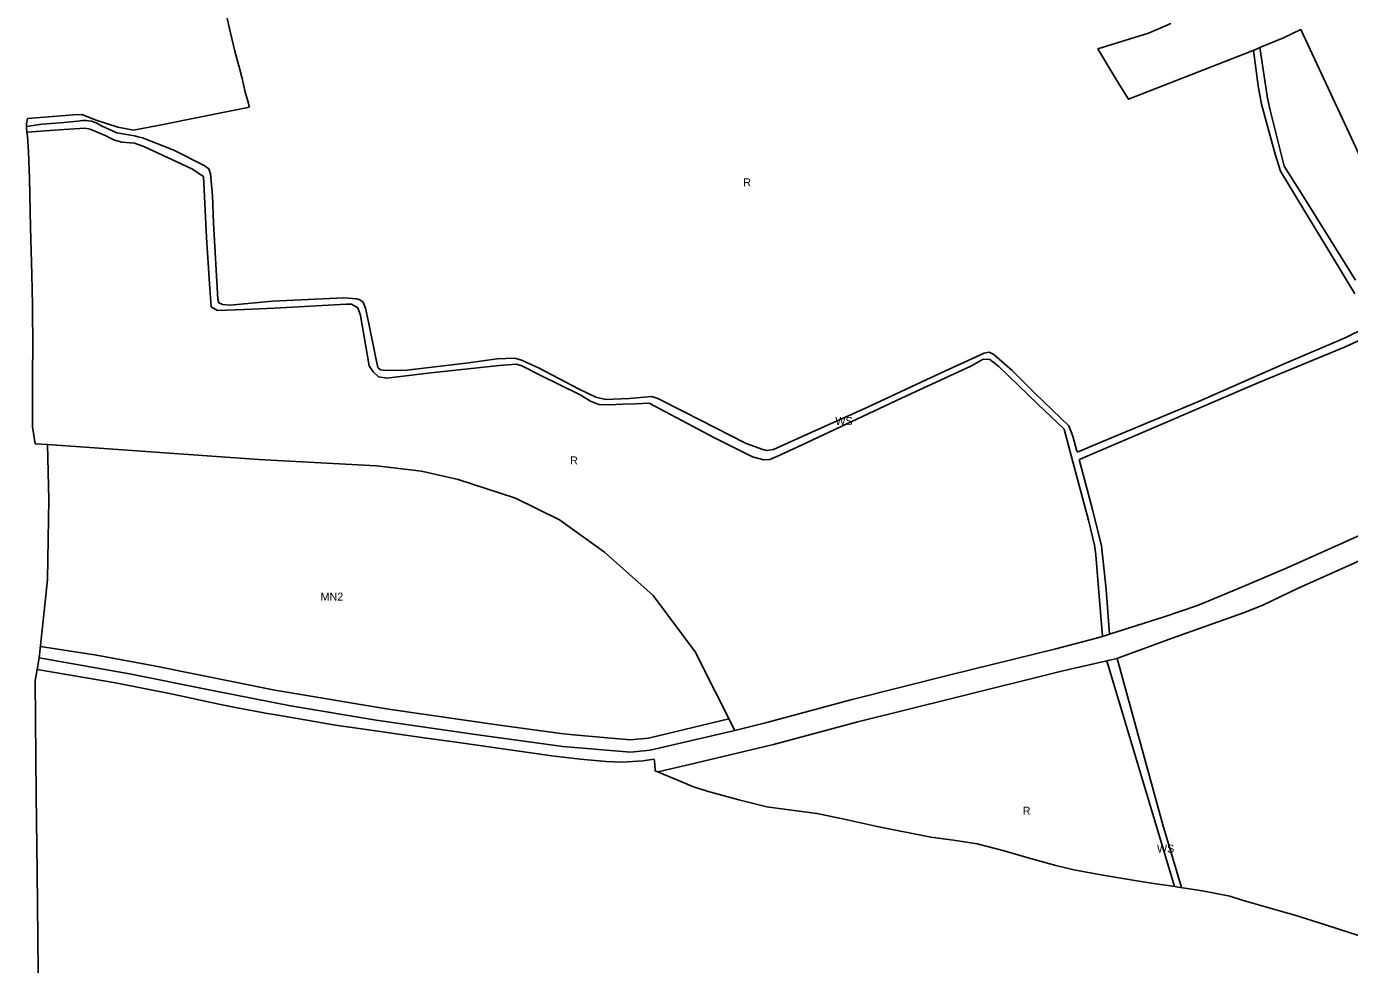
# Model space of a CAD drawing. Extents: x 7435758 to 7439981, y 5550649 to 5554049.
# Drawn here: x 7435758 to 7436617, y 5551099 to 5551708 of the extents above; entities that cross this region are included whole.
import ezdxf

# ---------------------------------------------------------------- set-up
doc = ezdxf.new("R2010")
doc.units = 0
for name, color, linetype in [('#Ruszcza', 7, 'Continuous'), ('_Tereny dla których obowiązuje MPZP', 7, 'Continuous'), ('linie_rozgraniczające', 7, 'Continuous'), ('linie_zabudowy_nieprzekraczalne', 7, 'Continuous'), ('oznaczenia_przeznaczen', 7, 'Continuous')]:
    doc.layers.add(name, color=color, linetype=linetype)

msp = doc.modelspace()

# ---------------------------------------------------------------- linework, layer by layer
at = {"layer": '#Ruszcza'}
for points in [[(7435764.91, 5551290.44), (7435763.61, 5551283.25), (7435764.25, 5551208.63), (7435764.51, 5551191.99), (7435764.91, 5551158.91), (7435765.29, 5551116.27), (7435765.64, 5551071.82), (7435762.19, 5551071.7), (7435762.39, 5551040.78), (7435762.64, 5551012.85), (7435763.34, 5550965.24), (7435763.42, 5550948.08), (7435763.51, 5550925.13)], [(7436649.61, 5551109.17), (7436611.08, 5551121.48), (7436601.18, 5551124.65), (7436581.32, 5551130.87), (7436576.56, 5551132.28), (7436547.71, 5551140.5), (7436539.6, 5551143.01), (7436521.94, 5551146.66), (7436506.12, 5551149.03), (7436503.85, 5551149.37), (7436490.05, 5551151.37), (7436476.69, 5551153.48), (7436457.24, 5551156.77), (7436438.37, 5551160.14), (7436426.54, 5551163.05), (7436407.16, 5551168.39), (7436393.06, 5551172.56), (7436375.57, 5551177.12), (7436360.06, 5551179.5), (7436345.33, 5551181.32), (7436310.46, 5551188.38), (7436291.18, 5551192.72), (7436285.08, 5551194), (7436271.4, 5551196.86), (7436253.31, 5551199.13), (7436240.5, 5551201.01), (7436238.82, 5551201.24), (7436220.63, 5551205.6), (7436200.03, 5551211.4), (7436191.25, 5551214.18), (7436183.03, 5551217.57), (7436180.38, 5551218.68), (7436166.33, 5551224.62), (7436166.04, 5551228.56), (7436165.89, 5551230.71), (7436165.79, 5551232.1), (7436161.13, 5551231.46), (7436158.49, 5551231.09), (7436144.77, 5551230.2), (7436139.82, 5551230.32), (7436134.57, 5551230.57), (7436117.71, 5551232.03), (7436099.24, 5551234.28), (7436038.66, 5551242.88), (7436016.37, 5551246.04), (7435972.54, 5551252.27), (7435958.63, 5551254.24), (7435920.04, 5551260.84), (7435914.57, 5551261.73), (7435894.9, 5551265.52), (7435882.8, 5551267.86), (7435851.87, 5551274.56), (7435815.73, 5551281.6), (7435764.91, 5551290.44)]]:
    msp.add_lwpolyline(points, dxfattribs=at)
at = {"layer": '_Tereny dla których obowiązuje MPZP'}
msp.add_line((7436555, 5551692.66), (7436558.29, 5551694.06), dxfattribs=at)
for points in [[(7436500.87, 5551710.27), (7436500.89, 5551709.81), (7436486.9, 5551703.76), (7436453.97, 5551693.56), (7436466.32, 5551673)], [(7436574.58, 5551700.76), (7436585.89, 5551706.11), (7436720.07, 5551418.24), (7436733.75, 5551423.85)], [(7436558.29, 5551694.06), (7436559.23, 5551694.45), (7436574.58, 5551700.76)], [(7436466.32, 5551673), (7436473.75, 5551660.92), (7436554.78, 5551692.57), (7436555, 5551692.66)]]:
    msp.add_lwpolyline(points, dxfattribs=at)
at = {"layer": 'linie_rozgraniczające'}
for p, q in [((7435890.47, 5551704), (7435887.2, 5551718.12)), ((7435893.21, 5551692.19), (7435890.47, 5551704)), ((7435895.24, 5551685.05), (7435893.21, 5551692.19)), ((7436555, 5551692.66), (7436558.29, 5551694.06)), ((7436555, 5551692.66), (7436558.03, 5551669.7)), ((7436564.11, 5551661.5), (7436559.23, 5551694.45)), ((7435895.94, 5551682.6), (7435895.24, 5551685.05)), ((7435896.63, 5551680.15), (7435895.94, 5551682.6)), ((7435897.99, 5551674.34), (7435896.63, 5551680.15)), ((7435899.35, 5551668.53), (7435897.99, 5551674.34)), ((7436558.03, 5551669.7), (7436560.18, 5551657.72)), ((7435899.85, 5551666.39), (7435899.35, 5551668.53)), ((7435900.35, 5551664.24), (7435899.85, 5551666.39)), ((7435901.24, 5551661.21), (7435900.35, 5551664.24)), ((7435902.14, 5551658.18), (7435901.24, 5551661.21)), ((7436565.91, 5551653.74), (7436564.11, 5551661.5)), ((7435868.1, 5551648.84), (7435902.76, 5551655.75)), ((7435902.45, 5551656.97), (7435902.14, 5551658.18)), ((7435902.76, 5551655.75), (7435902.45, 5551656.97)), ((7436560.18, 5551657.72), (7436569.22, 5551625.29)), ((7436574.95, 5551617.32), (7436565.91, 5551653.74)), ((7435767.94, 5551644.67), (7435757.92, 5551643.27)), ((7435757.94, 5551643.65), (7435758, 5551644.9)), ((7435758, 5551644.9), (7435758.49, 5551648.43)), ((7435758.49, 5551648.43), (7435788.37, 5551650.69)), ((7435771.19, 5551645.01), (7435767.94, 5551644.67)), ((7435779.88, 5551645.64), (7435771.19, 5551645.01)), ((7435791.24, 5551646.61), (7435779.88, 5551645.64)), ((7435788.37, 5551650.69), (7435793.96, 5551650.98)), ((7435794.38, 5551646.99), (7435791.24, 5551646.61)), ((7435793.96, 5551650.98), (7435803.21, 5551647.36)), ((7435796.84, 5551647.11), (7435794.38, 5551646.99)), ((7435798.19, 5551646.94), (7435796.84, 5551647.11)), ((7435800.14, 5551646.67), (7435798.19, 5551646.94)), ((7435803.2, 5551645.66), (7435800.14, 5551646.67)), ((7435807.12, 5551643.49), (7435803.2, 5551645.66)), ((7435803.21, 5551647.36), (7435817.37, 5551642.66)), ((7435827.37, 5551640.72), (7435847.75, 5551644.78)), ((7435847.75, 5551644.78), (7435868.1, 5551648.84)), ((7435757.92, 5551643.27), (7435757.94, 5551643.65)), ((7435757.99, 5551642.39), (7435757.92, 5551643.27)), ((7435758.21, 5551639.4), (7435757.99, 5551642.39)), ((7435758.21, 5551639.4), (7435779.15, 5551640.93)), ((7435758.23, 5551639.18), (7435758.21, 5551639.4)), ((7435758.61, 5551636.84), (7435758.23, 5551639.18)), ((7435759.17, 5551626.65), (7435758.61, 5551636.84)), ((7435779.15, 5551640.93), (7435795.82, 5551642.05)), ((7435795.82, 5551642.05), (7435799.23, 5551641.56)), ((7435799.23, 5551641.56), (7435809.09, 5551637.31)), ((7435814.16, 5551640.14), (7435807.12, 5551643.49)), ((7435809.09, 5551637.31), (7435815.11, 5551634.41)), ((7435816.72, 5551639.15), (7435814.16, 5551640.14)), ((7435828.03, 5551637.18), (7435816.72, 5551639.15)), ((7435817.37, 5551642.66), (7435827.37, 5551640.72)), ((7435830.38, 5551636.51), (7435828.03, 5551637.18)), ((7435833.41, 5551635.84), (7435830.38, 5551636.51)), ((7435853.6, 5551627.74), (7435833.41, 5551635.84)), ((7435815.11, 5551634.41), (7435819.95, 5551632.97)), ((7435819.95, 5551632.97), (7435828.02, 5551632.29)), ((7435828.02, 5551632.29), (7435834.26, 5551630.16)), ((7435834.26, 5551630.16), (7435865.27, 5551615.76)), ((7435873.35, 5551617.92), (7435853.6, 5551627.74)), ((7435759.83, 5551609.39), (7435759.17, 5551626.65)), ((7436569.22, 5551625.29), (7436572.53, 5551614.07)), ((7435865.27, 5551615.76), (7435872.89, 5551610.67)), ((7435872.89, 5551610.67), (7435874.87, 5551571.09)), ((7435876.46, 5551615.78), (7435873.35, 5551617.92)), ((7435877.47, 5551612.43), (7435876.46, 5551615.78)), ((7435878.68, 5551598.14), (7435877.47, 5551612.43)), ((7436572.53, 5551614.07), (7436588.07, 5551588.32)), ((7436588.35, 5551596.16), (7436574.95, 5551617.32)), ((7435760.47, 5551577.65), (7435759.83, 5551609.39)), ((7435879.53, 5551580.33), (7435878.68, 5551598.14)), ((7436621.2, 5551543.41), (7436588.35, 5551596.16)), ((7436588.07, 5551588.32), (7436610.73, 5551551.38)), ((7435761.45, 5551547.11), (7435760.47, 5551577.65)), ((7435882.15, 5551531.1), (7435879.53, 5551580.33)), ((7435874.87, 5551571.09), (7435876.72, 5551541.12)), ((7436610.73, 5551551.38), (7436620.92, 5551534.56)), ((7435761.87, 5551527.04), (7435761.45, 5551547.11)), ((7435876.72, 5551541.12), (7435877.96, 5551526.09)), ((7435761.96, 5551498.45), (7435761.87, 5551527.04)), ((7435877.96, 5551526.09), (7435881.95, 5551523.61)), ((7435881.95, 5551523.61), (7435899.28, 5551524.25)), ((7435882.88, 5551528.61), (7435882.15, 5551531.1)), ((7435885.31, 5551527.58), (7435882.88, 5551528.61)), ((7435890.23, 5551527.15), (7435885.31, 5551527.58)), ((7435917.66, 5551529.65), (7435890.23, 5551527.15)), ((7435899.28, 5551524.25), (7435919.1, 5551525.18)), ((7435964.08, 5551531.85), (7435917.66, 5551529.65)), ((7435919.1, 5551525.18), (7435965.63, 5551527.64)), ((7435972.53, 5551531.18), (7435964.08, 5551531.85)), ((7435965.63, 5551527.64), (7435969.03, 5551527.65)), ((7435969.03, 5551527.65), (7435973.27, 5551525.31)), ((7435974.44, 5551530.63), (7435972.53, 5551531.18)), ((7435973.27, 5551525.31), (7435974.98, 5551520.47)), ((7435976.64, 5551529.09), (7435974.44, 5551530.63)), ((7435978.18, 5551525.13), (7435976.64, 5551529.09)), ((7435980.34, 5551515.16), (7435978.18, 5551525.13)), ((7435974.98, 5551520.47), (7435980.58, 5551487.64)), ((7435984.6, 5551493.84), (7435980.34, 5551515.16)), ((7436614.1, 5551499.83), (7436632.56, 5551508.26)), ((7436628.7, 5551512.83), (7436614.59, 5551505.95)), ((7435761.89, 5551484.88), (7435761.96, 5551498.45)), ((7436558.6, 5551476.88), (7436614.1, 5551499.83)), ((7436614.59, 5551505.95), (7436574.99, 5551489.01)), ((7435986.28, 5551486.61), (7435984.6, 5551493.84)), ((7436044.99, 5551489.56), (7436005.08, 5551484.8)), ((7436063.61, 5551492.14), (7436044.99, 5551489.56)), ((7436075.16, 5551492.61), (7436063.61, 5551492.14)), ((7436079.48, 5551491.4), (7436075.16, 5551492.61)), ((7436090.49, 5551486.44), (7436079.48, 5551491.4)), ((7436379.97, 5551495.99), (7436352.08, 5551483.23)), ((7436371.76, 5551487.67), (7436379.51, 5551492.01)), ((7436379.51, 5551492.01), (7436383.79, 5551491.81)), ((7436383.22, 5551496.5), (7436379.97, 5551495.99)), ((7436386.42, 5551494.99), (7436383.22, 5551496.5)), ((7436383.79, 5551491.81), (7436389.63, 5551487.21)), ((7436398.16, 5551484.66), (7436386.42, 5551494.99)), ((7435761.89, 5551479.2), (7435761.89, 5551484.88)), ((7435980.58, 5551487.64), (7435983.13, 5551483.72)), ((7435983.13, 5551483.72), (7435986.65, 5551480.6)), ((7435987.85, 5551485.04), (7435986.28, 5551486.61)), ((7435986.65, 5551480.6), (7435992.1, 5551479.56)), ((7435991.39, 5551484.56), (7435987.85, 5551485.04)), ((7436005.08, 5551484.8), (7435991.39, 5551484.56)), ((7435992.1, 5551479.56), (7436018.61, 5551482.84)), ((7436018.61, 5551482.84), (7436065.04, 5551487.99)), ((7436065.04, 5551487.99), (7436076.32, 5551488.7)), ((7436076.32, 5551488.7), (7436079.76, 5551487.64)), ((7436079.76, 5551487.64), (7436091.69, 5551481.72)), ((7436116.95, 5551472.56), (7436090.49, 5551486.44)), ((7436091.69, 5551481.72), (7436117.61, 5551468.81)), ((7436352.08, 5551483.23), (7436302.99, 5551460.18)), ((7436326.35, 5551466.72), (7436371.76, 5551487.67)), ((7436389.63, 5551487.21), (7436415.01, 5551462.84)), ((7436413.62, 5551469.2), (7436398.16, 5551484.66)), ((7436574.99, 5551489.01), (7436518.82, 5551464.33)), ((7435761.89, 5551454.79), (7435761.89, 5551479.2)), ((7436127.72, 5551467.4), (7436116.95, 5551472.56)), ((7436527.79, 5551463.61), (7436558.6, 5551476.88)), ((7436117.61, 5551468.81), (7436124.31, 5551464.69)), ((7436124.31, 5551464.69), (7436129.67, 5551462.64)), ((7436134.07, 5551465.77), (7436127.72, 5551467.4)), ((7436138.96, 5551465.97), (7436134.07, 5551465.77)), ((7436149.5, 5551466.53), (7436138.96, 5551465.97)), ((7436164.28, 5551467.75), (7436149.5, 5551466.53)), ((7436153.66, 5551463.05), (7436162.45, 5551463.41)), ((7436162.45, 5551463.41), (7436204.97, 5551440.93)), ((7436167.98, 5551466.52), (7436164.28, 5551467.75)), ((7436184.8, 5551457.9), (7436167.98, 5551466.52)), ((7436261.84, 5551436.39), (7436326.35, 5551466.72)), ((7436435.07, 5551448.64), (7436413.62, 5551469.2)), ((7436518.82, 5551464.33), (7436453.95, 5551437.28)), ((7436498.1, 5551450.94), (7436527.79, 5551463.61)), ((7435761.76, 5551448.38), (7435761.89, 5551454.79)), ((7436129.67, 5551462.64), (7436136.22, 5551462.28)), ((7436136.22, 5551462.28), (7436145.38, 5551462.71)), ((7436145.38, 5551462.71), (7436153.66, 5551463.05)), ((7436225.48, 5551437.24), (7436184.8, 5551457.9)), ((7436302.99, 5551460.18), (7436268.17, 5551444.57)), ((7436415.01, 5551462.84), (7436432.01, 5551446.56)), ((7435761.75, 5551448.06), (7435761.76, 5551448.38)), ((7435763.6, 5551437.09), (7435761.75, 5551448.06)), ((7436432.01, 5551446.56), (7436436.88, 5551428.6)), ((7436437.59, 5551442.08), (7436435.07, 5551448.64)), ((7436442.48, 5551427.13), (7436498.1, 5551450.94)), ((7436204.97, 5551440.93), (7436229.61, 5551428.48)), ((7436268.17, 5551444.57), (7436243.24, 5551433.31)), ((7436440.26, 5551432.13), (7436437.59, 5551442.08)), ((7435763.64, 5551437.09), (7435763.6, 5551437.09)), ((7435771.55, 5551436.5), (7435763.64, 5551437.09)), ((7435772.41, 5551400.86), (7435771.55, 5551436.5)), ((7435908.88, 5551426.77), (7435771.55, 5551436.5)), ((7436236.33, 5551433.28), (7436225.48, 5551437.24)), ((7436238.74, 5551432.62), (7436236.33, 5551433.28)), ((7436243.24, 5551433.31), (7436238.74, 5551432.62)), ((7436245.31, 5551428.74), (7436261.84, 5551436.39)), ((7436441.04, 5551431.6), (7436440.26, 5551432.13)), ((7436441.1, 5551431.82), (7436441.04, 5551431.6)), ((7436453.95, 5551437.28), (7436441.1, 5551431.82)), ((7435985.28, 5551422.61), (7435908.88, 5551426.77)), ((7436014.45, 5551419.26), (7435985.28, 5551422.61)), ((7436229.61, 5551428.48), (7436236.85, 5551426.64)), ((7436236.85, 5551426.64), (7436240.73, 5551426.92)), ((7436240.73, 5551426.92), (7436245.31, 5551428.74)), ((7436436.88, 5551428.6), (7436447.86, 5551387.37)), ((7436441.81, 5551426.81), (7436442.48, 5551427.13)), ((7436450.47, 5551394.33), (7436441.81, 5551426.81)), ((7436038.27, 5551413.87), (7436014.45, 5551419.26)), ((7436075.51, 5551401.77), (7436038.27, 5551413.87)), ((7435771.69, 5551348.78), (7435772.41, 5551400.86)), ((7436104.23, 5551387.51), (7436075.51, 5551401.77)), ((7436133.43, 5551366.69), (7436104.23, 5551387.51)), ((7436447.86, 5551387.37), (7436451.78, 5551371.19)), ((7436456.33, 5551370.68), (7436450.47, 5551394.33)), ((7436656.21, 5551391.97), (7436576.92, 5551356.38)), ((7436583.63, 5551343.04), (7436662.06, 5551378.16)), ((7436451.78, 5551371.19), (7436452.55, 5551364.81)), ((7436459.36, 5551342.4), (7436456.33, 5551370.68)), ((7436164.98, 5551338.47), (7436133.43, 5551366.69)), ((7436452.55, 5551364.81), (7436454.06, 5551346.02)), ((7436576.92, 5551356.38), (7436546.75, 5551343.54)), ((7435770.15, 5551334.3), (7435771.69, 5551348.78)), ((7436454.06, 5551346.02), (7436456.86, 5551311.89)), ((7436546.75, 5551343.54), (7436525.97, 5551334.91)), ((7436561.17, 5551332.2), (7436583.63, 5551343.04)), ((7436192.32, 5551301.92), (7436164.98, 5551338.47)), ((7436461.4, 5551313.33), (7436459.36, 5551342.4)), ((7436525.97, 5551334.91), (7436518.57, 5551331.97)), ((7435766.25, 5551297.88), (7435770.15, 5551334.3)), ((7436518.57, 5551331.97), (7436497.08, 5551324.64)), ((7436502.25, 5551310.66), (7436548.45, 5551327.28)), ((7436548.45, 5551327.28), (7436561.17, 5551332.2)), ((7436497.08, 5551324.64), (7436461.4, 5551313.33)), ((7436452.23, 5551310.42), (7436426.71, 5551303.89)), ((7436456.86, 5551311.89), (7436452.23, 5551310.42)), ((7436456.86, 5551311.89), (7436461.4, 5551313.33)), ((7436466.89, 5551297.66), (7436502.25, 5551310.66)), ((7436218.05, 5551250.84), (7436192.32, 5551301.92)), ((7436426.71, 5551303.89), (7436358.09, 5551286.82)), ((7435824.87, 5551287.65), (7435766.25, 5551297.88)), ((7436430.38, 5551289.37), (7436459.7, 5551296.03)), ((7436466.37, 5551297.54), (7436459.7, 5551296.03)), ((7436459.7, 5551296.03), (7436503.71, 5551149.39)), ((7436466.37, 5551297.54), (7436466.89, 5551297.66)), ((7436496.23, 5551189.45), (7436466.37, 5551297.54)), ((7435878.67, 5551276.83), (7435824.87, 5551287.65)), ((7436358.09, 5551286.82), (7436293.52, 5551270.71)), ((7436361.62, 5551272.24), (7436430.38, 5551289.37)), ((7435929.51, 5551266.86), (7435878.67, 5551276.83)), ((7435985.14, 5551257.51), (7435929.51, 5551266.86)), ((7436293.52, 5551270.71), (7436238.85, 5551255.96)), ((7436297.98, 5551256.42), (7436361.62, 5551272.24)), ((7436051.09, 5551247.99), (7435985.14, 5551257.51)), ((7436218.05, 5551250.84), (7436163.13, 5551237.86)), ((7436238.85, 5551255.96), (7436218.05, 5551250.84)), ((7436243.31, 5551241.67), (7436297.98, 5551256.42)), ((7436106.37, 5551240.43), (7436051.09, 5551247.99)), ((7436150.36, 5551236.69), (7436106.37, 5551240.43)), ((7436192.29, 5551229.42), (7436243.31, 5551241.67)), ((7436163.13, 5551237.86), (7436150.36, 5551236.69)), ((7436168.18, 5551223.84), (7436169.13, 5551224.03)), ((7436169.13, 5551224.03), (7436192.29, 5551229.42)), ((7436508.19, 5551148.72), (7436496.23, 5551189.45))]:
    msp.add_line(p, q, dxfattribs=at)
for points in [[(7436500.87, 5551710.27), (7436500.89, 5551709.81), (7436486.9, 5551703.76), (7436453.97, 5551693.56), (7436466.32, 5551673)], [(7436574.58, 5551700.76), (7436585.89, 5551706.11), (7436720.07, 5551418.24), (7436733.75, 5551423.85)], [(7436558.29, 5551694.06), (7436559.23, 5551694.45), (7436574.58, 5551700.76)], [(7436466.32, 5551673), (7436473.75, 5551660.92), (7436554.78, 5551692.57), (7436555, 5551692.66)], [(7436649.61, 5551109.17), (7436611.08, 5551121.48), (7436601.18, 5551124.65), (7436581.32, 5551130.87), (7436576.56, 5551132.28), (7436547.71, 5551140.5), (7436539.6, 5551143.01), (7436521.94, 5551146.66), (7436506.12, 5551149.03), (7436503.85, 5551149.37), (7436490.05, 5551151.37), (7436476.69, 5551153.48), (7436457.24, 5551156.77), (7436438.37, 5551160.14), (7436426.54, 5551163.05), (7436407.16, 5551168.39), (7436393.06, 5551172.56), (7436375.57, 5551177.12), (7436360.06, 5551179.5), (7436345.33, 5551181.32), (7436310.46, 5551188.38), (7436291.18, 5551192.72), (7436285.08, 5551194), (7436271.4, 5551196.86), (7436253.31, 5551199.13), (7436240.5, 5551201.01), (7436238.82, 5551201.24), (7436220.63, 5551205.6), (7436200.03, 5551211.4), (7436191.25, 5551214.18), (7436183.03, 5551217.57), (7436180.38, 5551218.68), (7436166.33, 5551224.62), (7436166.04, 5551228.56), (7436165.89, 5551230.71), (7436165.79, 5551232.1), (7436161.13, 5551231.46), (7436158.49, 5551231.09), (7436144.77, 5551230.2), (7436139.82, 5551230.32), (7436134.57, 5551230.57), (7436117.71, 5551232.03), (7436099.24, 5551234.28), (7436038.66, 5551242.88), (7436016.37, 5551246.04), (7435972.54, 5551252.27), (7435958.63, 5551254.24), (7435920.04, 5551260.84), (7435914.57, 5551261.73), (7435894.9, 5551265.52), (7435882.8, 5551267.86), (7435851.87, 5551274.56), (7435815.73, 5551281.6), (7435764.91, 5551290.44), (7435766.25, 5551297.88)]]:
    msp.add_lwpolyline(points, dxfattribs=at)
at = {"layer": 'linie_zabudowy_nieprzekraczalne'}
msp.add_lwpolyline([(7435767.04, 5551305.3), (7435803.43, 5551299.58), (7435840.79, 5551292.83), (7435919.24, 5551277), (7435993.12, 5551264.56), (7436063.62, 5551254.48), (7436105.11, 5551248.68), (7436113.4, 5551247.93), (7436150.03, 5551244.68), (7436162.1, 5551245.83), (7436214.17, 5551258.38)], dxfattribs=at)

# ---------------------------------------------------------------- texts
at = {"layer": 'oznaczenia_przeznaczen'}
for s, p in [('R', (7436223.58, 5551604.3)), ('WS', (7436283.43, 5551449.23)), ('R', (7436111.1, 5551423.6)), ('MN2', (7435949.01, 5551335.1)), ('R', (7436405.18, 5551195.99)), ('WS', (7436492.34, 5551171.38))]:
    msp.add_text(s, height=5.2, dxfattribs=at).set_placement(p)

doc.saveas('drawing.dxf')
